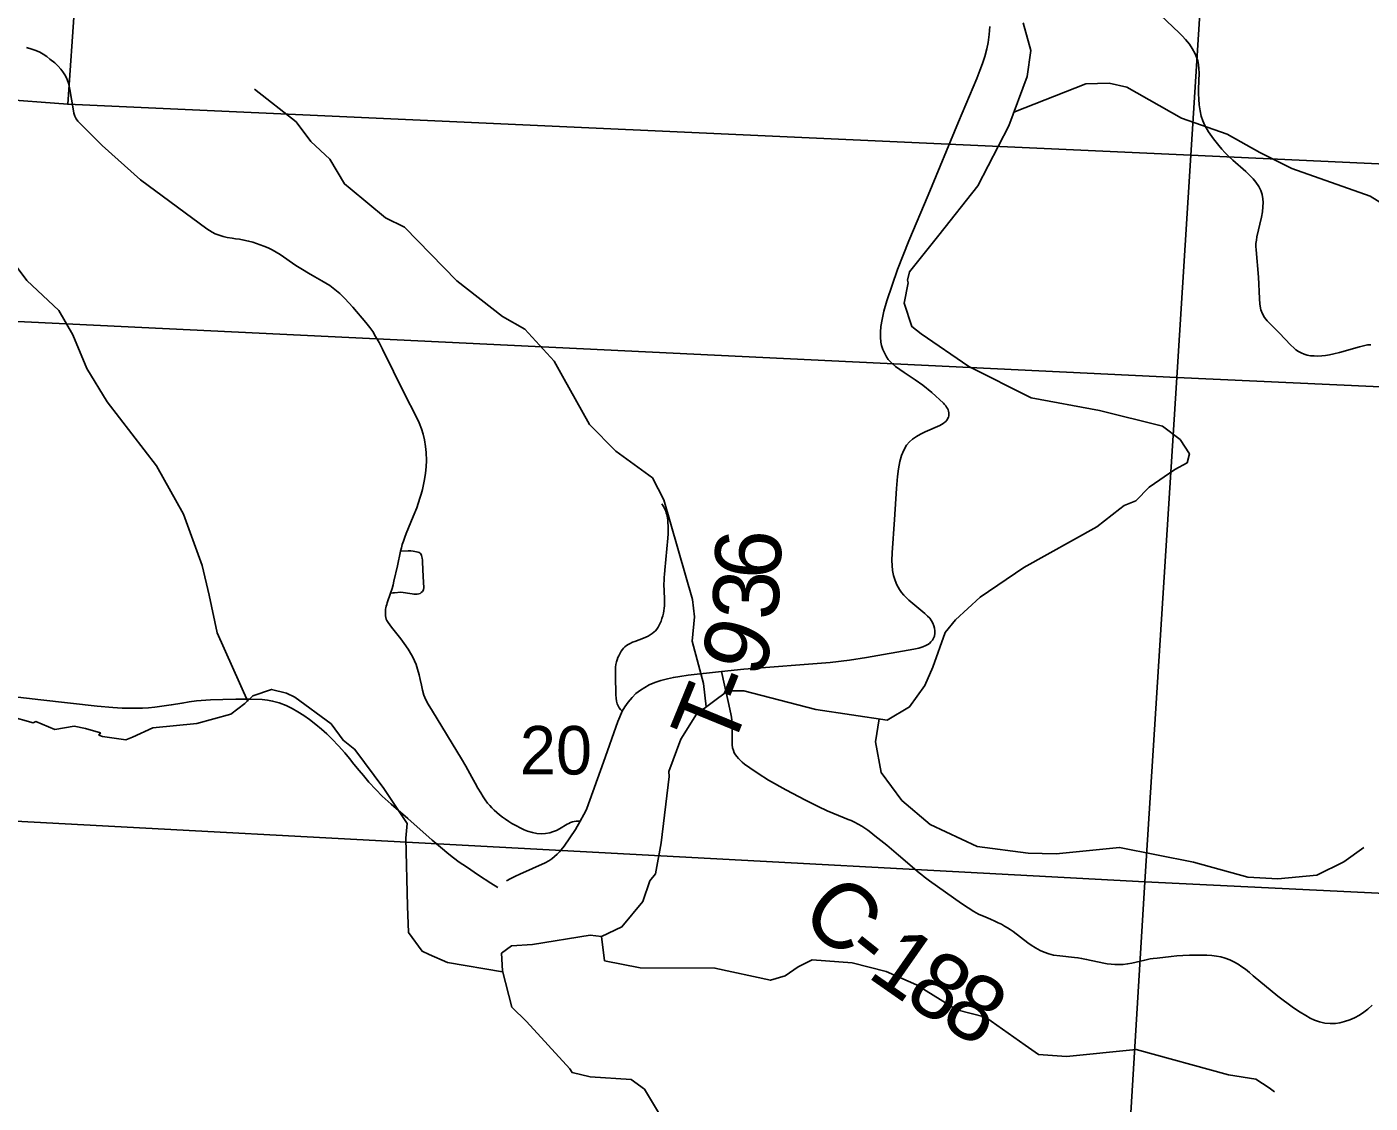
# Model space of a CAD drawing. Extents: x 0 to 34, y 0 to 22.
# Drawn here: x 2.913 to 4.072, y 14.479 to 15.408 of the extents above; entities that cross this region are included whole.
import ezdxf

# ---------------------------------------------------------------- set-up
doc = ezdxf.new("R2010")
doc.units = 0
for name, color, linetype in [('GM_X_County_Road', 7, 'Continuous'), ('GM_X_County_Road_Text', 7, 'Continuous'), ('GM_X_Minor_River', 7, 'Continuous'), ('GM_X_Section', 7, 'Continuous'), ('GM_X_Section_Text', 7, 'Continuous'), ('GM_X_State_Route', 7, 'Continuous'), ('GM_X_Township_Road', 7, 'Continuous'), ('GM_X_Township_Road_Text', 7, 'Continuous')]:
    doc.layers.add(name, color=color, linetype=linetype)

msp = doc.modelspace()

# ---------------------------------------------------------------- linework, layer by layer
at = {"layer": 'GM_X_County_Road'}
for points in [[(2.9127, 15.3902), (2.9172, 15.3888), (2.9208, 15.3875), (2.9241, 15.3862), (2.9271, 15.3844), (2.9301, 15.3825), (2.9329, 15.3802), (2.937, 15.3769), (2.94, 15.374), (2.9423, 15.3715), (2.9441, 15.3691), (2.9458, 15.3665), (2.9471, 15.3641), (2.9481, 15.3618), (2.9489, 15.3593), (2.9495, 15.3569), (2.9501, 15.3538), (2.9529, 15.3372), (2.9536, 15.3334), (2.9544, 15.3308), (2.9555, 15.3287), (2.9569, 15.3266), (2.9601, 15.3235), (2.9779, 15.3056), (3.0111, 15.276), (3.0682, 15.2337), (3.0704, 15.2321), (3.0727, 15.2308), (3.0755, 15.2294), (3.0788, 15.2281), (3.0824, 15.227), (3.0859, 15.2262), (3.0901, 15.2255), (3.093, 15.2251), (3.0964, 15.2246), (3.1002, 15.224), (3.1043, 15.2231), (3.108, 15.2221), (3.1112, 15.2211), (3.1143, 15.2199), (3.1174, 15.2187), (3.1211, 15.2171), (3.1245, 15.2155), (3.1281, 15.2135), (3.1316, 15.2115), (3.1451, 15.2021), (3.1508, 15.1984), (3.156, 15.1953), (3.1614, 15.1922), (3.1675, 15.1889), (3.1743, 15.1846), (3.1788, 15.1814), (3.183, 15.1778), (3.1874, 15.1734), (3.1941, 15.1661), (3.2055, 15.1528), (3.2089, 15.1484), (3.2114, 15.1449), (3.2138, 15.1408), (3.2168, 15.1354), (3.2199, 15.1297), (3.2387, 15.0911), (3.2488, 15.0717), (3.2513, 15.0662), (3.2534, 15.0609), (3.2549, 15.0564), (3.256, 15.0516), (3.257, 15.0458), (3.2575, 15.0405), (3.2577, 15.0338), (3.2575, 15.0283), (3.257, 15.0228), (3.2561, 15.0174), (3.2553, 15.0131), (3.2543, 15.0088), (3.2532, 15.0047), (3.2521, 15.0011), (3.2493, 14.9929), (3.2462, 14.9853), (3.2403, 14.9706), (3.2391, 14.9675), (3.2379, 14.964), (3.2369, 14.9611), (3.2361, 14.9584), (3.2353, 14.9554)], [(3.2353, 14.9554), (3.2326, 14.9427), (3.2297, 14.9295), (3.2291, 14.9264), (3.2282, 14.9232), (3.2268, 14.9192), (3.2239, 14.911), (3.2235, 14.9095), (3.223, 14.9079), (3.2227, 14.9066), (3.2225, 14.9055), (3.2224, 14.904), (3.2223, 14.9026), (3.2223, 14.9011), (3.2225, 14.8996), (3.2227, 14.8981), (3.2231, 14.8968), (3.2236, 14.8955), (3.2247, 14.8938), (3.2277, 14.8899), (3.2333, 14.8827), (3.2356, 14.8797), (3.2385, 14.8757), (3.242, 14.8709), (3.2448, 14.8661), (3.2462, 14.8635), (3.2474, 14.8607), (3.2487, 14.8575), (3.25, 14.8535), (3.2515, 14.8488), (3.2524, 14.8446), (3.2534, 14.8399), (3.2544, 14.8354), (3.2556, 14.8311), (3.2572, 14.8272), (3.2593, 14.8233), (3.2628, 14.8173), (3.2879, 14.7762), (3.2917, 14.7699), (3.297, 14.7604), (3.2997, 14.7553), (3.3021, 14.7509), (3.3045, 14.7469), (3.3066, 14.7435), (3.3085, 14.7408), (3.3105, 14.7381), (3.3124, 14.7359), (3.3142, 14.7339), (3.3162, 14.7319), (3.3183, 14.73), (3.3207, 14.728), (3.3232, 14.726), (3.3258, 14.7242), (3.3288, 14.7221), (3.3313, 14.7205), (3.3342, 14.7189), (3.3397, 14.716), (3.3421, 14.715), (3.3449, 14.7138), (3.3491, 14.7126), (3.3529, 14.7118), (3.3566, 14.7115), (3.3605, 14.7117), (3.3642, 14.7123), (3.3666, 14.7131), (3.3698, 14.7144), (3.3725, 14.7158), (3.3792, 14.7198), (3.3805, 14.7205), (3.382, 14.7212), (3.3836, 14.7218), (3.3851, 14.7221), (3.387, 14.7223), (3.3904, 14.7223)], [(3.5124, 14.8517), (3.515, 14.8397), (3.518, 14.8258), (3.5203, 14.8152), (3.5208, 14.8123), (3.5212, 14.8097), (3.5214, 14.8066), (3.5215, 14.8035), (3.5215, 14.7907), (3.5216, 14.7882), (3.5219, 14.7856), (3.5225, 14.7833), (3.5233, 14.7813), (3.5243, 14.7796), (3.5255, 14.7781), (3.5269, 14.7764), (3.5283, 14.775), (3.53, 14.7734), (3.5321, 14.7717), (3.5366, 14.7684), (3.5438, 14.7635), (3.5527, 14.7579), (3.5678, 14.7494), (3.5847, 14.7405), (3.5958, 14.735), (3.6034, 14.7314), (3.618, 14.7254), (3.6215, 14.724), (3.6241, 14.7229), (3.6269, 14.7215), (3.6302, 14.7198), (3.6334, 14.718), (3.6359, 14.7164), (3.6384, 14.7147), (3.6412, 14.7126), (3.6447, 14.7098), (3.6548, 14.7017), (3.6651, 14.6931), (3.6829, 14.6779), (3.685, 14.6761), (3.6872, 14.6743), (3.6894, 14.6726), (3.6916, 14.6709), (3.7194, 14.6515), (3.725, 14.6477), (3.73, 14.6446), (3.7341, 14.6423), (3.7402, 14.6395), (3.7443, 14.6378), (3.7481, 14.6361), (3.7509, 14.6348), (3.7537, 14.6334), (3.7565, 14.6319), (3.7591, 14.6305), (3.7614, 14.6289), (3.7638, 14.6272), (3.7767, 14.6175), (3.7794, 14.6155), (3.7833, 14.613), (3.7872, 14.6108), (3.7907, 14.6093), (3.7947, 14.6078), (3.7988, 14.6069), (3.8043, 14.6061), (3.8168, 14.6048), (3.8197, 14.6045), (3.823, 14.6039), (3.8272, 14.6031), (3.8422, 14.5999), (3.8451, 14.5993), (3.8484, 14.5989), (3.8517, 14.5987), (3.8556, 14.5986), (3.8589, 14.5988), (3.8626, 14.5992), (3.8664, 14.5999), (3.8774, 14.6026), (3.8797, 14.603), (3.8821, 14.6035), (3.8847, 14.6039), (3.888, 14.6043), (3.9001, 14.6056), (3.9052, 14.6061), (3.9104, 14.6065), (3.9159, 14.6067), (3.9208, 14.6069), (3.9265, 14.6069), (3.9311, 14.6067), (3.9354, 14.6064), (3.9393, 14.6059), (3.9431, 14.6053), (3.9469, 14.6042), (3.9507, 14.6027), (3.9543, 14.601), (3.9581, 14.599), (3.9613, 14.5968), (3.9644, 14.5947), (3.9677, 14.5918), (3.971, 14.5889), (3.9922, 14.5714), (4.0059, 14.5614), (4.0114, 14.5577), (4.0163, 14.5548), (4.0202, 14.5524), (4.024, 14.5507), (4.0283, 14.5491), (4.0329, 14.5481), (4.0375, 14.5478), (4.0419, 14.5478), (4.0457, 14.5484), (4.0498, 14.5495), (4.0543, 14.5511), (4.0584, 14.5528), (4.0627, 14.5551), (4.0665, 14.5575), (4.0699, 14.5602), (4.0736, 14.5636)], [(2.9002, 14.8299), (2.925, 14.827), (2.9735, 14.8218), (2.9872, 14.8205), (2.9952, 14.82), (3.0015, 14.8199), (3.0079, 14.8199), (3.0128, 14.82), (3.0179, 14.8203), (3.0233, 14.8208), (3.0295, 14.8216), (3.0375, 14.8228), (3.0469, 14.8244), (3.0531, 14.8254), (3.0594, 14.8262), (3.0713, 14.827), (3.0821, 14.8275), (3.0933, 14.8278), (3.1057, 14.8278), (3.1161, 14.8273), (3.1205, 14.8268), (3.1249, 14.8261), (3.1307, 14.8246), (3.1366, 14.8223), (3.142, 14.8197), (3.1468, 14.8169), (3.152, 14.8135), (3.1569, 14.8101), (3.1624, 14.8058), (3.1673, 14.8017), (3.1717, 14.7978), (3.1765, 14.7931), (3.1819, 14.7875), (3.1873, 14.7815), (3.1914, 14.7764), (3.1952, 14.7717), (3.1996, 14.7661), (3.2033, 14.7617), (3.2079, 14.7562), (3.2141, 14.7497), (3.2194, 14.7441), (3.2272, 14.737), (3.2416, 14.7246), (3.2627, 14.706), (3.2771, 14.694), (3.281, 14.6909), (3.286, 14.6871), (3.2922, 14.683), (3.3025, 14.6758), (3.3134, 14.669), (3.3192, 14.6653)]]:
    msp.add_lwpolyline(points, dxfattribs=at)
at = {"layer": 'GM_X_Minor_River'}
for points in [[(3.1037, 14.8257), (3.0772, 14.885), (3.0702, 14.9175), (3.0642, 14.9431), (3.0482, 14.9873), (3.0249, 15.029), (2.9823, 15.0843), (2.9647, 15.113), (2.9527, 15.1422), (2.9405, 15.1631), (2.9129, 15.189), (2.9002, 15.2061), (2.8874, 15.2323), (2.848, 15.3171), (2.831, 15.3412), (2.8274, 15.3493), (2.815, 15.3744), (2.8078, 15.3997), (2.8048, 15.4248), (2.8005, 15.4333)], [(3.4579, 14.4711), (3.4458, 14.4912), (3.4344, 14.4996), (3.3989, 14.5018), (3.3834, 14.5055), (3.3815, 14.5086), (3.344, 14.5495), (3.3315, 14.562), (3.3232, 14.5932), (3.3224, 14.6084), (3.3311, 14.6148), (3.3492, 14.616), (3.3991, 14.6241), (3.4086, 14.623), (3.4263, 14.6311), (3.4445, 14.6531), (3.4505, 14.671), (3.4554, 14.6771), (3.4603, 14.7037), (3.4671, 14.7611), (3.4667, 14.7653), (3.4772, 14.7931), (3.4908, 14.8148), (3.5176, 14.835), (3.5316, 14.835), (3.5936, 14.8189), (3.6553, 14.8095), (3.6745, 14.821), (3.6877, 14.8396), (3.6945, 14.8552), (3.7051, 14.8853), (3.7141, 14.8963), (3.7353, 14.9158), (3.7731, 14.9413), (3.8362, 14.9765), (3.8558, 14.9921), (3.8596, 14.9948), (3.8698, 14.999), (3.8811, 15.0108), (3.9034, 15.026), (3.914, 15.0318), (3.9159, 15.0394), (3.9079, 15.0519), (3.8928, 15.0633), (3.8383, 15.0768), (3.7794, 15.0877), (3.7257, 15.1149), (3.6844, 15.1429), (3.6765, 15.1493), (3.67, 15.1695), (3.6734, 15.187), (3.6727, 15.1892), (3.6746, 15.1965), (3.6999, 15.2281), (3.7335, 15.2707), (3.7603, 15.3225), (3.7761, 15.3651), (3.7791, 15.3875), (3.7726, 15.4115)], [(3.7646, 15.3342), (3.8266, 15.3588), (3.8466, 15.3593), (3.862, 15.3558), (3.9092, 15.3292), (3.9485, 15.3154), (3.9767, 15.2994), (4.0043, 15.2856), (4.072, 15.2618), (4.0938, 15.2482), (4.1749, 15.1902), (4.1916, 15.1676), (4.1984, 15.156), (4.2053, 15.133), (4.2357, 15.0781), (4.2408, 15.0723), (4.255, 15.0528), (4.2723, 15.0367)], [(3.4991, 14.821), (3.4967, 14.8412), (3.4869, 14.8779), (3.489, 14.8987), (3.4872, 14.9136), (3.4626, 14.9998), (3.4526, 15.0187), (3.4211, 15.0417), (3.3984, 15.0649), (3.3751, 15.1066), (3.3679, 15.1194), (3.3427, 15.1471), (3.3234, 15.158), (3.2839, 15.1888), (3.2388, 15.2351), (3.2224, 15.2432), (3.1918, 15.2684), (3.187, 15.2724), (3.1744, 15.2937), (3.1579, 15.309), (3.1452, 15.3261), (3.1093, 15.3542)], [(3.3234, 14.5924), (3.2759, 14.6003), (3.26, 14.6074), (3.254, 14.6101), (3.2423, 14.6264), (3.2415, 14.6492), (3.2399, 14.7077), (3.241, 14.7203), (3.221, 14.7506), (3.196, 14.7844), (3.1858, 14.7923), (3.1756, 14.8064), (3.1442, 14.8295), (3.137, 14.8329), (3.1241, 14.8362), (3.1079, 14.8305), (3.1011, 14.824), (3.089, 14.8149), (3.0595, 14.8068), (3.0217, 14.8029), (3.004, 14.7949), (2.9983, 14.7926), (2.9783, 14.7956), (2.9752, 14.7967), (2.9764, 14.7986), (2.9635, 14.8024), (2.9537, 14.8043), (2.937, 14.8016), (2.9208, 14.8084), (2.9185, 14.8072), (2.8981, 14.8129)], [(3.6483, 14.8106), (3.645, 14.7909), (3.65, 14.7643), (3.6678, 14.7404), (3.6922, 14.7196), (3.7328, 14.7006), (3.7768, 14.6947), (3.8011, 14.6943), (3.8557, 14.6998), (3.9194, 14.687), (3.9665, 14.6742), (3.9923, 14.6727), (4.026, 14.6758), (4.0491, 14.6873), (4.0665, 14.6998)], [(3.4086, 14.623), (3.4114, 14.6019), (3.4421, 14.5959), (3.5066, 14.5956), (3.5544, 14.5851), (3.5673, 14.5889), (3.5783, 14.5966), (3.5904, 14.6027), (3.6249, 14.6001), (3.6542, 14.5926), (3.6804, 14.5812), (3.7153, 14.5596), (3.74, 14.5532), (3.7742, 14.529), (3.7859, 14.521), (3.8098, 14.5192), (3.8701, 14.5254), (3.9498, 14.5035), (3.9733, 14.4998), (3.9847, 14.4922), (3.9893, 14.4888)]]:
    msp.add_lwpolyline(points, dxfattribs=at)
at = {"layer": 'GM_X_Section'}
for points in [[(3.0046, 16.1593), (2.9664, 15.604), (2.9483, 15.3412), (2.8868, 15.3457), (2.8841, 15.3459), (2.9352, 16.1608)], [(2.9664, 15.604), (3.7495, 15.5685), (3.9339, 15.5602), (3.9173, 15.2973), (2.9483, 15.3412)], [(3.9339, 15.5602), (4.383, 15.5384), (4.9066, 15.513), (4.889, 15.2523), (3.9173, 15.2973)], [(2.9483, 15.3412), (3.9173, 15.2973), (3.9051, 15.1052), (2.8751, 15.155), (2.8868, 15.3457)], [(4.889, 15.2523), (4.958, 15.2491), (4.9464, 15.0576), (3.9051, 15.1052), (3.9173, 15.2973)], [(2.8751, 15.155), (3.9051, 15.1052), (3.8776, 14.6701), (2.8494, 14.7254)], [(3.9051, 15.1052), (4.9464, 15.0576), (4.92, 14.6193), (3.8776, 14.6701)], [(3.8776, 14.6701), (3.8519, 14.2476), (2.8265, 14.2988), (2.8494, 14.7254)], [(4.92, 14.6193), (4.8918, 14.1721), (4.0883, 14.232), (3.8519, 14.2476), (3.8776, 14.6701)]]:
    msp.add_lwpolyline(points, close=True, dxfattribs=at)
at = {"layer": 'GM_X_State_Route'}
for points in [[(4.0726, 15.1336), (4.0697, 15.1334), (4.0662, 15.1328), (4.0627, 15.1319), (4.0455, 15.1269), (4.0405, 15.1257), (4.0368, 15.125), (4.0333, 15.1244), (4.0301, 15.1241), (4.0267, 15.1238), (4.0235, 15.1239), (4.0204, 15.1241), (4.0176, 15.1246), (4.0151, 15.1254), (4.0125, 15.1265), (4.0101, 15.1278), (4.0079, 15.1293), (4.006, 15.131), (4.0036, 15.1333), (3.9934, 15.144), (3.9829, 15.1543), (3.9806, 15.1572), (3.9789, 15.1603), (3.9775, 15.1638), (3.9768, 15.1687), (3.9763, 15.1735), (3.9755, 15.1918), (3.9736, 15.2154), (3.9733, 15.2183), (3.9734, 15.2211), (3.9737, 15.2239), (3.9742, 15.2268), (3.9781, 15.2437), (3.9789, 15.2483), (3.9794, 15.2526), (3.9796, 15.2563), (3.9794, 15.2594), (3.9786, 15.2634), (3.9775, 15.2667), (3.9758, 15.2702), (3.9734, 15.2739), (3.9711, 15.2768), (3.9685, 15.2794), (3.9646, 15.2831), (3.9534, 15.293), (3.95, 15.2961), (3.9466, 15.2994), (3.9438, 15.3025), (3.9412, 15.3055), (3.9367, 15.3113), (3.9325, 15.3175), (3.9293, 15.3228), (3.9275, 15.3269), (3.9262, 15.3309), (3.9251, 15.3356), (3.9244, 15.3407), (3.924, 15.3455), (3.9239, 15.3502), (3.9239, 15.3542), (3.9243, 15.3684), (3.9241, 15.3718), (3.9238, 15.3754), (3.9231, 15.3785), (3.922, 15.3817), (3.9208, 15.3848), (3.9184, 15.3892), (3.9159, 15.3929), (3.9125, 15.3971), (3.9098, 15.4001), (3.9074, 15.4025), (3.8853, 15.4234)], [(3.3268, 14.6708), (3.3305, 14.673), (3.3344, 14.675), (3.3382, 14.6767), (3.3601, 14.6865), (3.3633, 14.6883), (3.366, 14.69), (3.3682, 14.6918), (3.3704, 14.6938), (3.3725, 14.696), (3.3765, 14.7008), (3.3864, 14.7151), (3.3904, 14.7223), (3.3936, 14.7282), (3.3949, 14.7309), (3.396, 14.7334), (3.4106, 14.7734), (3.4229, 14.8083), (3.4246, 14.8125), (3.4267, 14.8173), (3.429, 14.8211), (3.4317, 14.8252), (3.4352, 14.8292), (3.4385, 14.8326), (3.4423, 14.8355), (3.446, 14.8379), (3.4499, 14.84), (3.4547, 14.842), (3.4598, 14.8437), (3.4657, 14.8453), (3.4708, 14.8465), (3.4763, 14.8474), (3.4835, 14.8485), (3.5124, 14.8517), (3.5314, 14.8537), (3.606, 14.8595), (3.6227, 14.8615), (3.6375, 14.8638), (3.6781, 14.8708), (3.6825, 14.8718), (3.686, 14.8729), (3.6887, 14.874), (3.6902, 14.8749), (3.6916, 14.8759), (3.693, 14.8771), (3.6943, 14.8786), (3.6953, 14.8803), (3.6959, 14.8822), (3.6963, 14.8847), (3.6963, 14.8868), (3.696, 14.8889), (3.6954, 14.8911), (3.6945, 14.8932), (3.6934, 14.8954), (3.6919, 14.8975), (3.6901, 14.8994), (3.6878, 14.9017), (3.674, 14.9131), (3.6715, 14.9156), (3.6695, 14.9176), (3.6676, 14.9199), (3.6657, 14.9224), (3.6636, 14.9263), (3.662, 14.93), (3.6606, 14.9345), (3.6597, 14.9389), (3.6594, 14.943), (3.6593, 14.9474), (3.6594, 14.9541), (3.6614, 14.9829), (3.6632, 15.0095), (3.6641, 15.0198), (3.665, 15.0266), (3.6661, 15.0329), (3.6675, 15.0379), (3.6696, 15.0426), (3.6719, 15.0468), (3.6745, 15.0498), (3.6771, 15.0521), (3.6804, 15.0544), (3.684, 15.0565), (3.6881, 15.0584), (3.7005, 15.0638), (3.7022, 15.0647), (3.7036, 15.0657), (3.705, 15.0667), (3.7059, 15.0675), (3.7067, 15.0684), (3.7072, 15.0693), (3.7076, 15.0701), (3.708, 15.0711), (3.7083, 15.0722), (3.7084, 15.0736), (3.7083, 15.0749), (3.7081, 15.0763), (3.7078, 15.0774), (3.7073, 15.0785), (3.7065, 15.0797), (3.7057, 15.0809), (3.7048, 15.0819), (3.7037, 15.0832), (3.6937, 15.0924), (3.6859, 15.0986), (3.6793, 15.1034), (3.67, 15.1097), (3.6625, 15.1149), (3.6599, 15.1171), (3.658, 15.1188), (3.6561, 15.1209), (3.6547, 15.1232), (3.6528, 15.1266), (3.6515, 15.1295), (3.6504, 15.1329), (3.6498, 15.1359), (3.6494, 15.1401), (3.6494, 15.1444), (3.6498, 15.1493), (3.6508, 15.1553), (3.6524, 15.1625), (3.655, 15.1715), (3.6642, 15.1985), (3.6739, 15.2234), (3.6907, 15.2628), (3.7166, 15.3261), (3.7325, 15.3634), (3.7352, 15.3702), (3.7374, 15.3763), (3.7395, 15.3823), (3.7413, 15.389), (3.7424, 15.3945), (3.7433, 15.4014), (3.7437, 15.4082)]]:
    msp.add_lwpolyline(points, dxfattribs=at)
at = {"layer": 'GM_X_Township_Road'}
for points in [[(3.4267, 14.8173), (3.4251, 14.8189), (3.4241, 14.8203), (3.4231, 14.8219), (3.4222, 14.8238), (3.4216, 14.8261), (3.4213, 14.8287), (3.4211, 14.8315), (3.4207, 14.8479), (3.4207, 14.8507), (3.4207, 14.853), (3.4209, 14.8552), (3.4211, 14.8575), (3.4216, 14.8598), (3.4222, 14.8617), (3.4229, 14.8636), (3.4236, 14.8651), (3.4245, 14.8669), (3.4258, 14.869), (3.4268, 14.8705), (3.4278, 14.8717), (3.429, 14.8729), (3.4303, 14.8739), (3.4317, 14.8749), (3.4334, 14.8758), (3.4354, 14.8768), (3.4374, 14.8776), (3.4451, 14.8805), (3.4471, 14.8813), (3.4491, 14.8822), (3.4507, 14.8832), (3.4524, 14.8844), (3.4538, 14.8855), (3.4552, 14.8868), (3.4564, 14.8882), (3.4575, 14.8898), (3.4584, 14.8915), (3.4593, 14.8932), (3.4601, 14.895), (3.4609, 14.8972), (3.4616, 14.8996), (3.4622, 14.902), (3.4626, 14.904), (3.4629, 14.9062), (3.4631, 14.9084), (3.4632, 14.9113), (3.4632, 14.9142), (3.4626, 14.9273), (3.4627, 14.9302), (3.4628, 14.933), (3.463, 14.9354), (3.4633, 14.939), (3.466, 14.9666), (3.4662, 14.9704), (3.4663, 14.9739), (3.4662, 14.9773), (3.4661, 14.98), (3.4659, 14.9822), (3.4656, 14.9841), (3.4654, 14.9856), (3.465, 14.9872), (3.4646, 14.9886), (3.4641, 14.99), (3.4634, 14.9916), (3.4621, 14.9941), (3.4609, 14.9962)], [(3.2268, 14.9192), (3.2288, 14.9194), (3.2302, 14.9195), (3.2357, 14.9201), (3.2455, 14.9185), (3.2469, 14.9184), (3.2486, 14.9183), (3.2498, 14.9184), (3.251, 14.9186), (3.2522, 14.919), (3.2533, 14.9197), (3.2543, 14.9207), (3.2548, 14.9215), (3.2552, 14.9225), (3.2554, 14.9238), (3.255, 14.9336), (3.2544, 14.946), (3.2542, 14.9478), (3.254, 14.9493), (3.2538, 14.9506), (3.2534, 14.9518), (3.2531, 14.9526), (3.2526, 14.9533), (3.252, 14.9539), (3.2513, 14.9544), (3.2503, 14.9547), (3.2491, 14.955), (3.2478, 14.9552), (3.2463, 14.9554), (3.2442, 14.9556), (3.242, 14.9556), (3.2353, 14.9554)]]:
    msp.add_lwpolyline(points, dxfattribs=at)

# ---------------------------------------------------------------- texts
at = {"layer": 'GM_X_County_Road_Text'}
for s, rotation, p in [('C', 318.857, (3.578, 14.6382)), ('-', 321.3811, (3.6152, 14.6058)), ('1', 325.1055, (3.6367, 14.5888)), ('8', 328.1275, (3.6681, 14.567)), ('8', 329.4883, (3.6991, 14.5477))]:
    msp.add_text(s, height=0.0568, rotation=rotation, dxfattribs=at).set_placement(p)
at = {"layer": 'GM_X_Section_Text'}
msp.add_text('20', height=0.04186, rotation=0, dxfattribs=at).set_placement((3.3383, 14.7627))
at = {"layer": 'GM_X_Township_Road_Text'}
for s, rotation, p in [('6', 87.3367, (3.5626, 14.9304)), ('3', 87.3, (3.5609, 14.8954)), ('9', 70.4444, (3.5457, 14.8446)), ('-', 68.0876, (3.5361, 14.8206)), ('T', 67.7744, (3.5199, 14.781))]:
    msp.add_text(s, height=0.0568, rotation=rotation, dxfattribs=at).set_placement(p)

doc.saveas('drawing.dxf')
